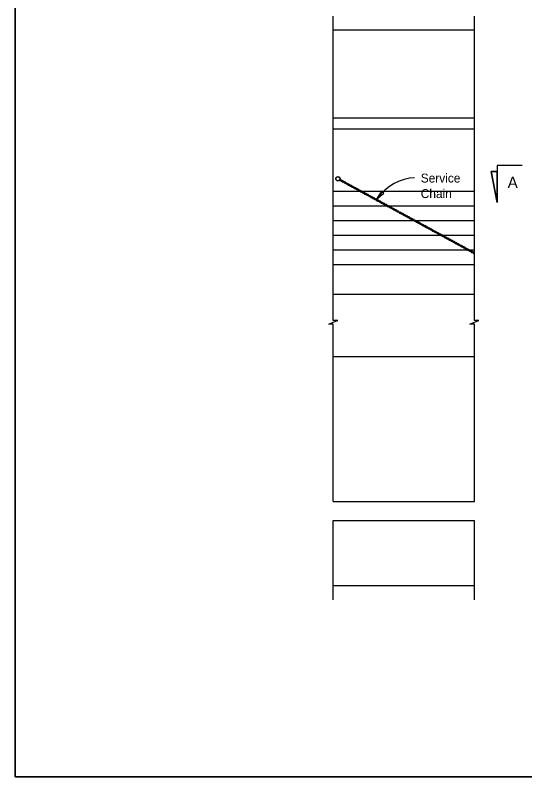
# Model space of a CAD drawing. Extents: x 0 to 20.5, y 0 to 13.
# Drawn here: x 0 to 5.78, y 0 to 8.64 of the extents above; entities that cross this region are included whole.
import ezdxf

# ---------------------------------------------------------------- set-up
doc = ezdxf.new("R2010")
doc.units = 0
for name, color, linetype in [('ActivePts-ConstElements', 7, 'Continuous'), ('Dimension', 7, 'Continuous'), ('Miscellaneous', 7, 'Continuous'), ('Miscellaneous1', 7, 'Continuous'), ('NavLight_h', 7, 'Continuous'), ('SupstrConc', 7, 'Continuous'), ('TextStructures', 7, 'Continuous')]:
    doc.layers.add(name, color=color, linetype=linetype)

msp = doc.modelspace()

# ---------------------------------------------------------------- linework, layer by layer
at = {"layer": 'ActivePts-ConstElements'}
msp.add_lwpolyline([(0, 0), (20.5253, 0), (20.5253, 12.9731), (0, 12.9731)], close=True, dxfattribs=at)
at = {"layer": 'Dimension'}
for p, q in [((5.7448, 6.9359), (5.4635, 6.9359)), ((5.4635, 6.9359), (5.4635, 6.514)), ((5.4635, 6.514), (5.3932, 6.8656)), ((5.3932, 6.8656), (5.4635, 6.8656))]:
    msp.add_line(p, q, dxfattribs=at)
for points in [[(3.6051, 3.1215), (3.6051, 5.1331), (3.5535, 5.1331), (3.6051, 5.1556), (3.6568, 5.1781), (3.6051, 5.1781), (3.6051, 8.6305)], [(5.2042, 3.1215), (5.2042, 5.1331), (5.1525, 5.1331), (5.2042, 5.1556), (5.2559, 5.1781), (5.2042, 5.1781), (5.2042, 8.6305)], [(3.6051, 3.1215), (5.2042, 3.1215)], [(3.6051, 2.0075), (3.6051, 2.9088)], [(3.6051, 2.9088), (5.2042, 2.9088)], [(5.2042, 2.0075), (5.2042, 2.9088)]]:
    msp.add_lwpolyline(points, dxfattribs=at)
for points in [[(5.4635, 6.8656), (5.3932, 6.8656), (5.4635, 6.514)], [(4.0944, 6.5539), (4.1765, 6.6203), (4.1501, 6.6436)]]:
    msp.add_lwpolyline(points, close=True, dxfattribs=at)
msp.add_ellipse((4.5272, 5.7637), major_axis=(0.001, -1.0298), ratio=0.654738, start_param=3.141603, end_param=3.837005, dxfattribs=at)
at = {"layer": 'Miscellaneous'}
for radius in [0.0241, 0.0222]:
    msp.add_circle((3.6577, 6.7848), radius, dxfattribs=at)
for centre, major_axis, ratio in [((3.6885, 6.7671), (-0.0135, 0.0073), 0.530594), ((3.6885, 6.7671), (-0.0117, 0.0064), 0.458548), ((3.7118, 6.7544), (-0.0135, 0.0073), 0.530594), ((3.7118, 6.7544), (-0.0117, 0.0064), 0.458548), ((3.7351, 6.7417), (-0.0135, 0.0073), 0.530594), ((3.7351, 6.7417), (-0.0117, 0.0064), 0.458548), ((3.7585, 6.7289), (-0.0135, 0.0073), 0.530594), ((3.7585, 6.7289), (-0.0117, 0.0064), 0.458548), ((3.7818, 6.7162), (-0.0135, 0.0073), 0.530594), ((3.7818, 6.7162), (-0.0117, 0.0064), 0.458548), ((3.8051, 6.7035), (-0.0135, 0.0073), 0.530594), ((3.8051, 6.7035), (-0.0117, 0.0064), 0.458548), ((3.8284, 6.6908), (-0.0135, 0.0073), 0.530594), ((3.8284, 6.6908), (-0.0117, 0.0064), 0.458548), ((3.8518, 6.678), (-0.0135, 0.0073), 0.530594), ((3.8518, 6.678), (-0.0117, 0.0064), 0.458548), ((3.8751, 6.6653), (-0.0135, 0.0073), 0.530594), ((3.8751, 6.6653), (-0.0117, 0.0064), 0.458548), ((3.8984, 6.6526), (-0.0135, 0.0073), 0.530594), ((3.8984, 6.6526), (-0.0117, 0.0064), 0.458548), ((3.9217, 6.6399), (-0.0135, 0.0073), 0.530594), ((3.9217, 6.6399), (-0.0117, 0.0064), 0.458548), ((3.945, 6.6272), (-0.0135, 0.0073), 0.530594), ((3.945, 6.6272), (-0.0117, 0.0064), 0.458548), ((3.9684, 6.6144), (-0.0135, 0.0073), 0.530594), ((3.9684, 6.6144), (-0.0117, 0.0064), 0.458548), ((3.9917, 6.6017), (-0.0135, 0.0073), 0.530594), ((3.9917, 6.6017), (-0.0117, 0.0064), 0.458548), ((4.015, 6.589), (-0.0135, 0.0073), 0.530594), ((4.015, 6.589), (-0.0117, 0.0064), 0.458548), ((4.0383, 6.5763), (-0.0135, 0.0073), 0.530594), ((4.0383, 6.5763), (-0.0117, 0.0064), 0.458548), ((4.0617, 6.5636), (-0.0135, 0.0073), 0.530594), ((4.0617, 6.5636), (-0.0117, 0.0064), 0.458548), ((4.085, 6.5508), (-0.0135, 0.0073), 0.530594), ((4.085, 6.5508), (-0.0117, 0.0064), 0.458548), ((4.1083, 6.5381), (-0.0135, 0.0073), 0.530594), ((4.1083, 6.5381), (-0.0117, 0.0064), 0.458548), ((4.1316, 6.5254), (-0.0135, 0.0073), 0.530594), ((4.1316, 6.5254), (-0.0117, 0.0064), 0.458548), ((4.155, 6.5127), (-0.0135, 0.0073), 0.530594), ((4.155, 6.5127), (-0.0117, 0.0064), 0.458548), ((4.1783, 6.5), (-0.0135, 0.0073), 0.530594), ((4.1783, 6.5), (-0.0117, 0.0064), 0.458548), ((4.2016, 6.4872), (-0.0135, 0.0073), 0.530594), ((4.2016, 6.4872), (-0.0117, 0.0064), 0.458548), ((4.2249, 6.4745), (-0.0135, 0.0073), 0.530594), ((4.2249, 6.4745), (-0.0117, 0.0064), 0.458548), ((4.2482, 6.4618), (-0.0135, 0.0073), 0.530594), ((4.2482, 6.4618), (-0.0117, 0.0064), 0.458548), ((4.2716, 6.4491), (-0.0135, 0.0073), 0.530594), ((4.2716, 6.4491), (-0.0117, 0.0064), 0.458548), ((4.2949, 6.4364), (-0.0135, 0.0073), 0.530594), ((4.2949, 6.4364), (-0.0117, 0.0064), 0.458548), ((4.3182, 6.4236), (-0.0135, 0.0073), 0.530594), ((4.3182, 6.4236), (-0.0117, 0.0064), 0.458548), ((4.3415, 6.4109), (-0.0135, 0.0073), 0.530594), ((4.3415, 6.4109), (-0.0117, 0.0064), 0.458548), ((4.3649, 6.3982), (-0.0135, 0.0073), 0.530594), ((4.3649, 6.3982), (-0.0117, 0.0064), 0.458548), ((4.3882, 6.3855), (-0.0135, 0.0073), 0.530594), ((4.3882, 6.3855), (-0.0117, 0.0064), 0.458548), ((4.4115, 6.3728), (-0.0135, 0.0073), 0.530594), ((4.4115, 6.3728), (-0.0117, 0.0064), 0.458548), ((4.4348, 6.36), (-0.0135, 0.0073), 0.530594), ((4.4348, 6.36), (-0.0117, 0.0064), 0.458548), ((4.4582, 6.3473), (-0.0135, 0.0073), 0.530594), ((4.4582, 6.3473), (-0.0117, 0.0064), 0.458548), ((4.4815, 6.3346), (-0.0135, 0.0073), 0.530594), ((4.4815, 6.3346), (-0.0117, 0.0064), 0.458548), ((4.5048, 6.3219), (-0.0135, 0.0073), 0.530594), ((4.5048, 6.3219), (-0.0117, 0.0064), 0.458548), ((4.5281, 6.3091), (-0.0135, 0.0073), 0.530594), ((4.5281, 6.3091), (-0.0117, 0.0064), 0.458548), ((4.5514, 6.2964), (-0.0135, 0.0073), 0.530594), ((4.5514, 6.2964), (-0.0117, 0.0064), 0.458548), ((4.5748, 6.2837), (-0.0135, 0.0073), 0.530594), ((4.5748, 6.2837), (-0.0117, 0.0064), 0.458548), ((4.5981, 6.271), (-0.0135, 0.0073), 0.530594), ((4.5981, 6.271), (-0.0117, 0.0064), 0.458548), ((4.6214, 6.2583), (-0.0135, 0.0073), 0.530594), ((4.6214, 6.2583), (-0.0117, 0.0064), 0.458548), ((4.6447, 6.2455), (-0.0135, 0.0073), 0.530594), ((4.6447, 6.2455), (-0.0117, 0.0064), 0.458548), ((4.6681, 6.2328), (-0.0135, 0.0073), 0.530594), ((4.6681, 6.2328), (-0.0117, 0.0064), 0.458548), ((4.6914, 6.2201), (-0.0135, 0.0073), 0.530594), ((4.6914, 6.2201), (-0.0117, 0.0064), 0.458548), ((4.7147, 6.2074), (-0.0135, 0.0073), 0.530594), ((4.7147, 6.2074), (-0.0117, 0.0064), 0.458548), ((4.738, 6.1947), (-0.0135, 0.0073), 0.530594), ((4.738, 6.1947), (-0.0117, 0.0064), 0.458548), ((4.7614, 6.1819), (-0.0135, 0.0073), 0.530594), ((4.7614, 6.1819), (-0.0117, 0.0064), 0.458548), ((4.7847, 6.1692), (-0.0135, 0.0073), 0.530594), ((4.7847, 6.1692), (-0.0117, 0.0064), 0.458548), ((4.808, 6.1565), (-0.0135, 0.0073), 0.530594), ((4.808, 6.1565), (-0.0117, 0.0064), 0.458548), ((4.8313, 6.1438), (-0.0135, 0.0073), 0.530594), ((4.8313, 6.1438), (-0.0117, 0.0064), 0.458548), ((4.8546, 6.1311), (-0.0135, 0.0073), 0.530594), ((4.8546, 6.1311), (-0.0117, 0.0064), 0.458548), ((4.878, 6.1183), (-0.0135, 0.0073), 0.530594), ((4.878, 6.1183), (-0.0117, 0.0064), 0.458548), ((4.9013, 6.1056), (-0.0135, 0.0073), 0.530594), ((4.9013, 6.1056), (-0.0117, 0.0064), 0.458548), ((4.9246, 6.0929), (-0.0135, 0.0073), 0.530594), ((4.9246, 6.0929), (-0.0117, 0.0064), 0.458548), ((4.9479, 6.0802), (-0.0135, 0.0073), 0.530594), ((4.9479, 6.0802), (-0.0117, 0.0064), 0.458548), ((4.9713, 6.0675), (-0.0135, 0.0073), 0.530594), ((4.9713, 6.0675), (-0.0117, 0.0064), 0.458548), ((4.9946, 6.0547), (-0.0135, 0.0073), 0.530594), ((4.9946, 6.0547), (-0.0117, 0.0064), 0.458548), ((5.0179, 6.042), (-0.0135, 0.0073), 0.530594), ((5.0179, 6.042), (-0.0117, 0.0064), 0.458548), ((5.0412, 6.0293), (-0.0135, 0.0073), 0.530594), ((5.0412, 6.0293), (-0.0117, 0.0064), 0.458548), ((5.0646, 6.0166), (-0.0135, 0.0073), 0.530594), ((5.0646, 6.0166), (-0.0117, 0.0064), 0.458548), ((5.0879, 6.0039), (-0.0135, 0.0073), 0.530594), ((5.0879, 6.0039), (-0.0117, 0.0064), 0.458548), ((5.1112, 5.9911), (-0.0135, 0.0073), 0.530594), ((5.1112, 5.9911), (-0.0117, 0.0064), 0.458548), ((5.1345, 5.9784), (-0.0135, 0.0073), 0.530594), ((5.1345, 5.9784), (-0.0117, 0.0064), 0.458548), ((5.1578, 5.9657), (-0.0135, 0.0073), 0.530594), ((5.1578, 5.9657), (-0.0117, 0.0064), 0.458548), ((5.1812, 5.953), (-0.0135, 0.0073), 0.530594), ((5.1812, 5.953), (-0.0117, 0.0064), 0.458548)]:
    msp.add_ellipse(centre, major_axis=major_axis, ratio=ratio, dxfattribs=at)
for major_axis, ratio, start_param, end_param in [((-0.0135, 0.0073), 0.530594, 5.015995, 8.113767), ((-0.0117, 0.0064), 0.458548, 4.982983, 8.073526)]:
    msp.add_ellipse((5.2045, 5.9403), major_axis=major_axis, ratio=ratio, start_param=start_param, end_param=end_param, dxfattribs=at)
at = {"layer": 'Miscellaneous1'}
msp.add_lwpolyline([(0, 12.9731), (20.5253, 12.9731), (20.5253, 0), (0, 0)], close=True, dxfattribs=at)
at = {"layer": 'NavLight_h'}
for p, q in [((5.2042, 6.6416), (3.6051, 6.6416)), ((5.2042, 6.4749), (3.6051, 6.4749)), ((5.2042, 6.3082), (3.6051, 6.3082)), ((5.2042, 6.1415), (3.6051, 6.1415)), ((5.2042, 5.9749), (3.6051, 5.9749)), ((5.2042, 5.8082), (3.6051, 5.8082))]:
    msp.add_line(p, q, dxfattribs=at)
at = {"layer": 'SupstrConc'}
for p, q in [((3.6051, 8.4748), (5.2042, 8.4748)), ((3.6051, 7.4748), (5.2042, 7.4748)), ((3.6051, 7.3498), (5.2042, 7.3498)), ((3.6051, 5.4749), (5.2042, 5.4749)), ((3.6051, 4.7666), (5.2042, 4.7666)), ((3.6051, 2.1697), (5.2042, 2.1697))]:
    msp.add_line(p, q, dxfattribs=at)

# ---------------------------------------------------------------- texts
at = {"layer": 'Dimension'}
for s, p in [('Service', (4.5966, 6.7417)), ('Chain', (4.5966, 6.5657))]:
    msp.add_text(s, height=0.1008, dxfattribs=at).set_placement(p)
at = {"layer": 'TextStructures'}
msp.add_text('A', height=0.128, dxfattribs=at).set_placement((5.5818, 6.6793))

doc.saveas('drawing.dxf')
